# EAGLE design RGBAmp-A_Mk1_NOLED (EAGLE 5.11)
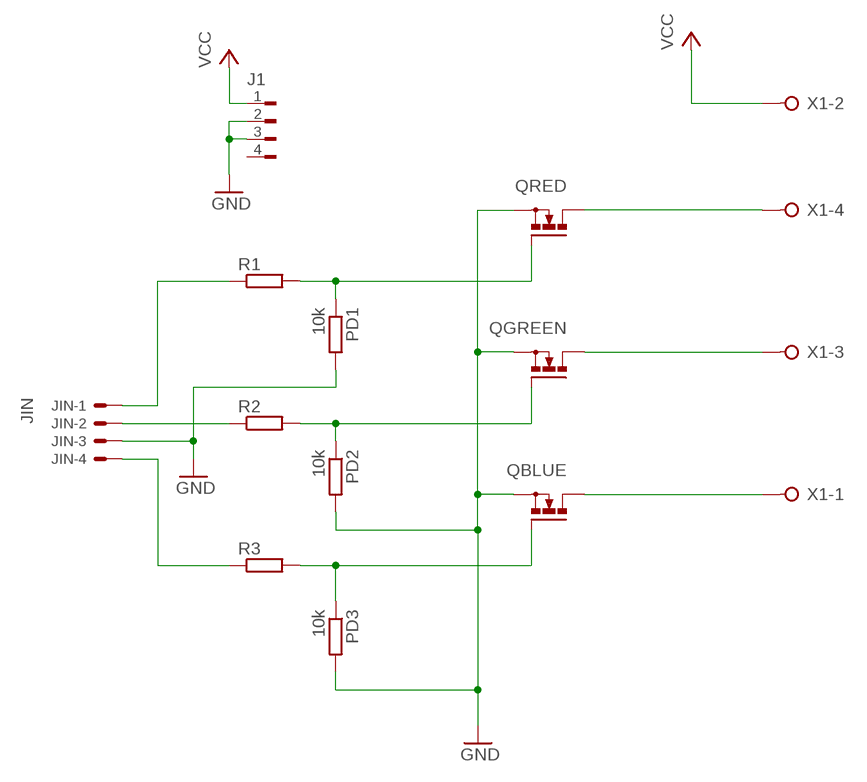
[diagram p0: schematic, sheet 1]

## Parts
J1  FLOPPY-4  [FLOPPY-4]
JIN  JIN  22-27-2041-04  [6410-04]
PD1  10k  R-EU_0207/2V  [0207/2V]
PD2  10k  R-EU_0207/2V  [0207/2V]
PD3  10k  R-EU_0207/2V  [0207/2V]
QBLUE  PMOSFET_NTO220BV  [TO220BV]
QGREEN  PMOSFET_NTO220BV  [TO220BV]
QRED  PMOSFET_NTO220BV  [TO220BV]
R1  R-EU_0207/10  [0207/10]
R2  R-EU_0207/7  [0207/7]
R3  R-EU_0207/5V  [0207/5V]
X1  W237-04P  [W237-4P]

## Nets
GND: J1.2 J1.3 JIN.3 PD1.2 PD2.2 PD3.2 QBLUE.S QGREEN.S QRED.S
N$1: PD1.1 QRED.G R1.2
N$2: PD2.1 QGREEN.G R2.2
N$3: PD3.1 QBLUE.G R3.2
N$4: JIN.4 R3.1
N$5: JIN.2 R2.1
N$6: JIN.1 R1.1
N$7: QRED.D X1.4
N$8: QGREEN.D X1.3
N$9: QBLUE.D X1.1
VCC: J1.1 X1.2
Unconnected: J1.4

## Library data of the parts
J1 = con-amp:FLOPPY-4: MATE N-LOCK Floppy / HDD conector Distributor: Bürklin 71F970; OC_FARNELL: unknown; OC_NEWARK: unknown
JIN = con-molex:22-?-04: CONNECTOR wire to board 2.54 mm (.1 inch) pitch header; OC_FARNELL: unknown; OC_NEWARK: unknown
PD1-PD3 = resistor:R-EU_: RESISTOR, European symbol
QBLUE QGREEN QRED = transistor-power:PMOSFET_N: Power MOSFET N-Channel
R1-R3 = rcl:R-EU_: RESISTOR, European symbol
X1 = con-wago-508:W237-04P: WAGO SREW CLAMP; OC_FARNELL: unknown; OC_NEWARK: unknown

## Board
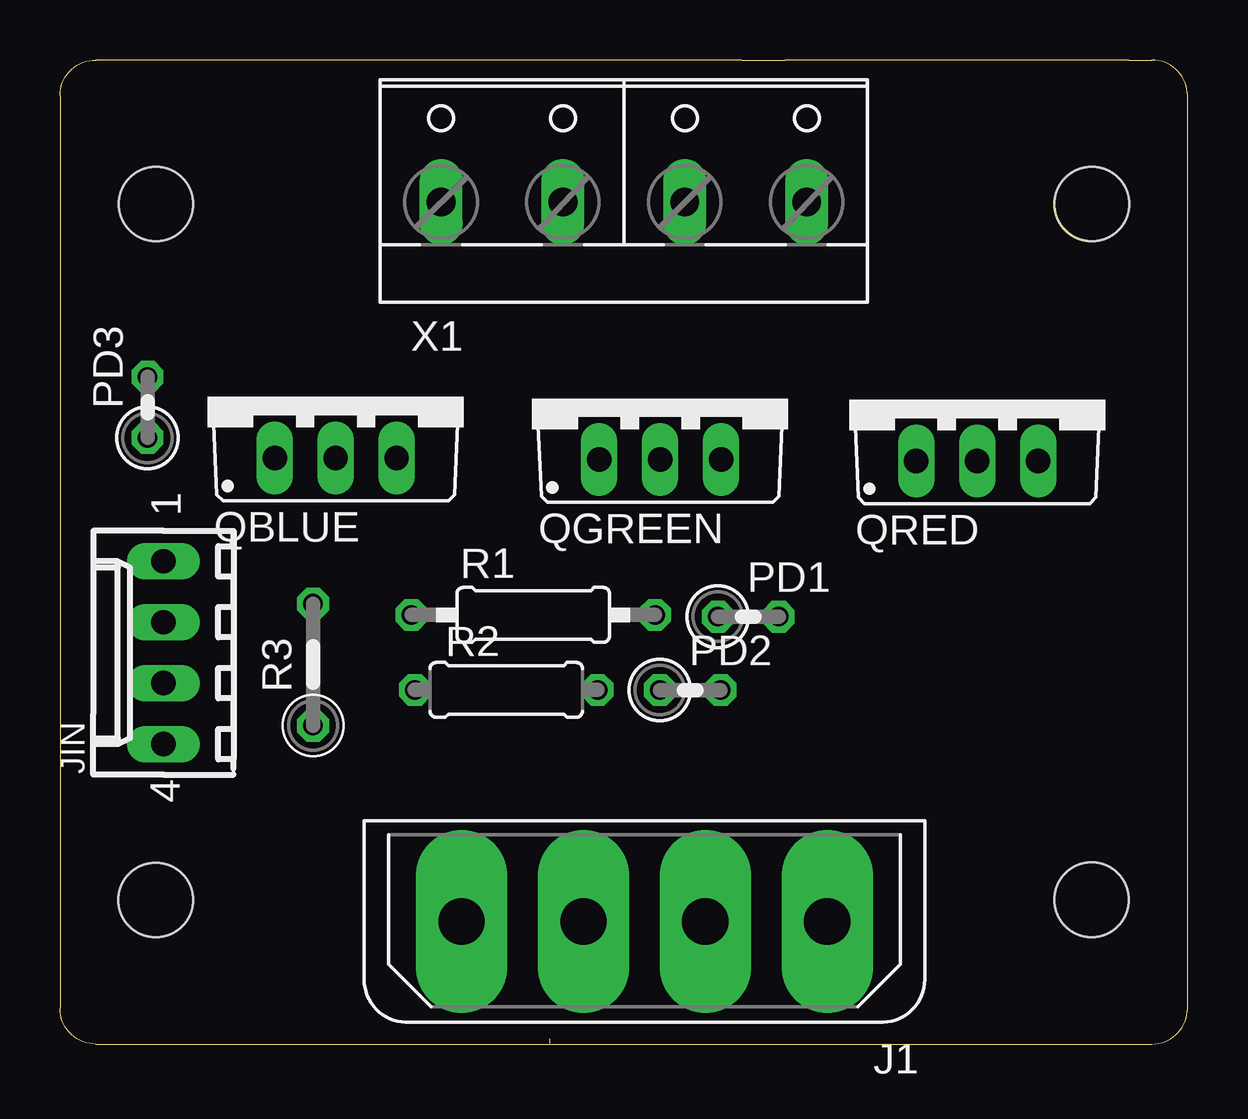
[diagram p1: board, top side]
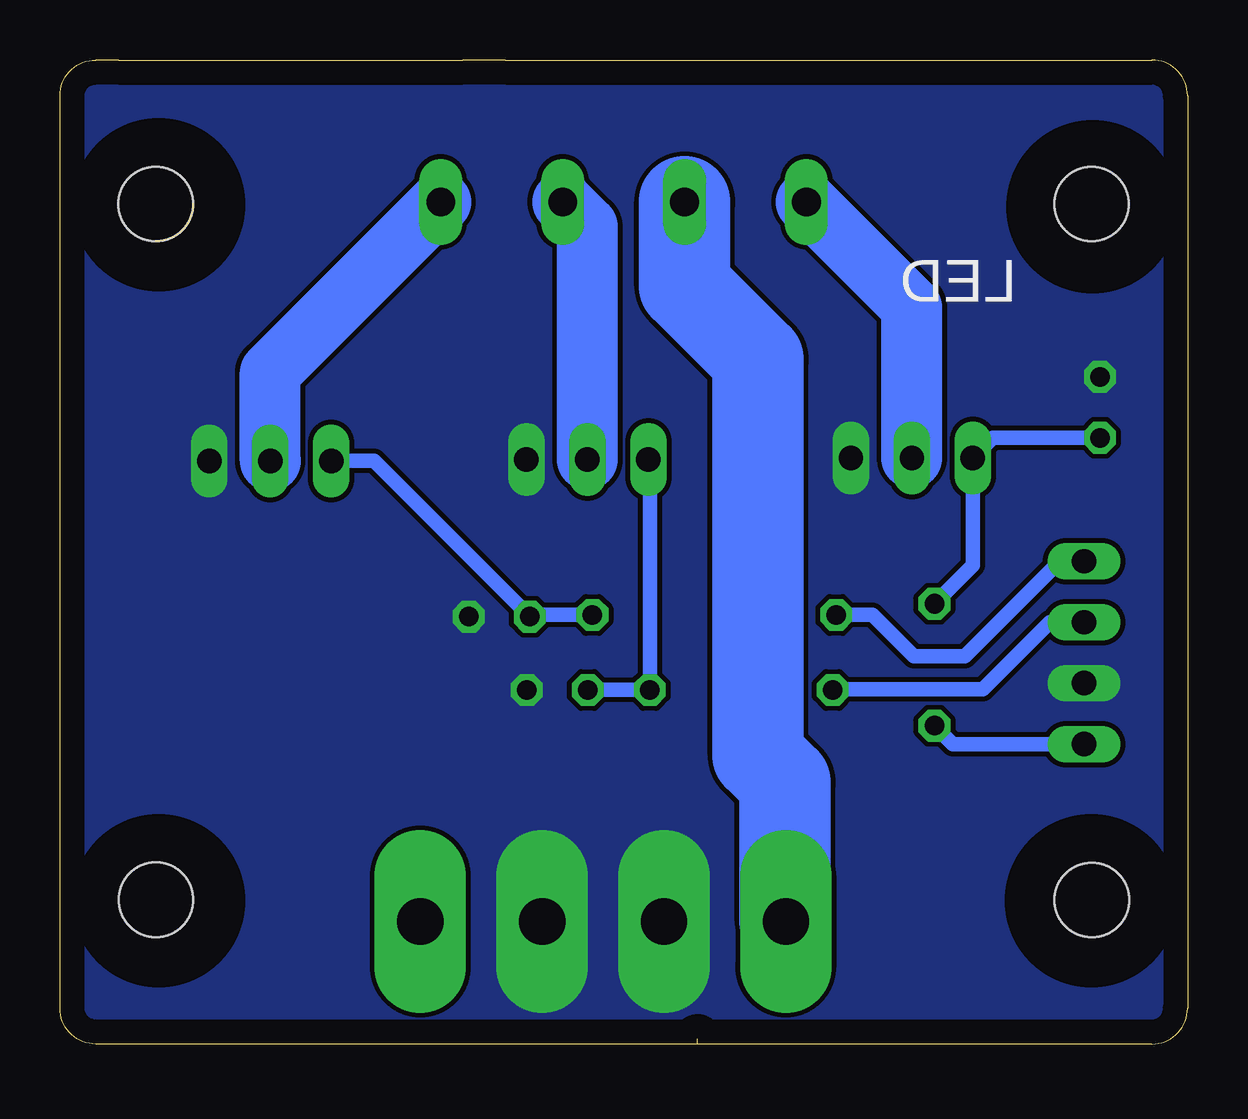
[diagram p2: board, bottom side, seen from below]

Size 47 x 41 mm. Coordinates in mm from the lower left corner, seen from the top.
Outline: 20.43,0.03 20.43,0.23
Outline: 41.44,35.03 arc90 43.02,33.45 43.03,33.45
Outline: 44.55,41 45.51,41 arc-90 47,39.51 47,1.49 arc-90 45.51,0 1.49,0 arc-90 0,1.49 0,39.51 arc-90 1.49,41 28.43,41 30.21,41 44.55,41
Copper layers (1*16): Top 0.035mm / dielectric 1.5mm / Bottom 0.035mm
Design rules "default": minimum track width 10mil, minimum drill 24mil, track to track 8mil, track to pad 8mil, pad to pad 8mil, via to via 8mil, smd to smd 8mil, copper to edge 40mil, drill to drill 8mil, minimum pad ring 10mil, minimum via ring 8mil, stop-mask expansion 4mil, vias tented up to drill 0mil, thermal gap 10mil
Holes 3.1 mm at 43,6.01 3.99,6 4,35 43.01,35
bKeepout: area 0.4,31.3 to 7.6,38.5; area 0.4,2.4 to 7.6,9.6; area 39.3,2.4 to 46.5,9.6; area 39.3,31.4 to 46.5,38.6
tRestrict: area 0.4,31.3 to 7.6,38.5; area 0.4,2.4 to 7.6,9.6; area 39.3,2.4 to 46.5,9.6; area 39.3,31.4 to 46.5,38.6
bRestrict: area 0.4,31.3 to 7.6,38.5; area 0.4,2.4 to 7.6,9.6; area 39.3,2.4 to 46.5,9.6; area 39.3,31.4 to 46.5,38.6

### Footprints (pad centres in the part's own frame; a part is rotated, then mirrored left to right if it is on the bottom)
FLOPPY-4 = drill 1.93 pad 3.81 long: 1 7.62,0; 2 2.54,0; 3 -2.54,0; 4 -7.62,0
6410-04 = drill 1.016 long: 1 3.81,0; 2 1.27,0; 3 -1.27,0; 4 -3.81,0
0207/2V = drill 0.813 octagon: 1 -1.27,0; 2 1.27,0
TO220BV = drill 1.016 long: D 0,-2.54; G -2.54,-2.54; S 2.54,-2.54
0207/10 = drill 0.813 octagon: 1 -5.08,0; 2 5.08,0
0207/7 = drill 0.813 octagon: 1 -3.81,0; 2 3.81,0
0207/5V = drill 0.813 octagon: 1 -2.54,0; 2 2.54,0
W237-4P = drill 1.194 long: 1 -7.62,-0.635; 2 -2.54,-0.635; 3 2.54,-0.635; 4 7.62,-0.635

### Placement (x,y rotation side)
J1  24.36,5.1 180 top
JIN  4.32,16.3 90 top
PD1  28.69,17.8 0 top
PD2  26.27,14.75 0 top
PD3  3.65,26.53 90 top
QBLUE  11.49,26.96 0 top
QGREEN  25.02,26.89 0 top
QRED  38.23,26.84 0 top
R1  19.73,17.88 0 top
R2  18.6,14.75 0 top
R3  10.55,15.8 90 top
X1  23.51,35.72 0 top

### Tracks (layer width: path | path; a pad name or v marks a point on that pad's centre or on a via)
GND
  pour Bottom (no thermals): 0.03,39.53 1.28,41.03 45.53,41.03 47.03,39.78 47.03,1.53 45.53,0.03 1.53,0.03 0.03,1.53
N$1
  Bottom 0.61: QRED.G 33.92,24.3 27.5,17.88 27.4,17.88 | R1.2 27.4,17.88 | PD1.1 27.42,17.86 27.4,17.88
N$2
  Bottom 0.61: QGREEN.G 22.41,24.29 R2.2 PD2.1
N$3
  Bottom 0.61: R3.2 8.95,19.94 QBLUE.G 8.11,25.26 PD3.1
N$4
  Bottom 0.61: R3.1 9.78,12.49 JIN.4
N$5
  Bottom 0.61: JIN.2 5.73,17.57 8.53,14.78 14.77,14.78 R2.1
N$6
  Bottom 0.61: R1.1 13.13,17.88 11.4,16.15 9.28,16.15 5.28,20.15 4.53,20.15 | 4.53,20.15 4.36,20.15 | JIN.1 4.49,20.11 4.53,20.15
N$7
  Bottom 2.54: QRED.D 38.23,27.98 X1.4
N$8
  Bottom 2.54: QGREEN.D 25.02,34.06 X1.3
N$9
  Bottom 2.54: QBLUE.D 11.49,30.69 X1.1
VCC
  Bottom 3.81: X1.2 20.97,31.59 17.9,28.53 17.9,12.03 16.78,10.9 16.78,5.14 J1.1

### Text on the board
tOrigins: LED_POS
bNames: LED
